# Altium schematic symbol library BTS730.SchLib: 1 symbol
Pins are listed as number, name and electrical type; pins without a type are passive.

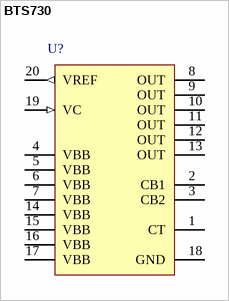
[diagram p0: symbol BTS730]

## BTS730
designator U?
Smart High-Side Power Switch, 1 Channel, 3 A Load Current, -40 to 150 degC, PG-DSO-20-31, Reel, Green; Manufacturer: Infineon; PartNumber: BTS730; Channels: 1; Green: TRUE; Group: Automotive Qualified; Load Current (typ): 3 A; Ptot (max): 3 W; Recommended Operating Voltage Max.: 16.9 V; Recommended Operating Voltage Min.: 5.9 V; RON @ 25degreesC: 70 mOhm; RON(max) @ 150degreesC: 140 mOhm
footprint INF-PG-DSO-20-31_N (SOP, 20-Leads, Body 12.7x7.5mm, Pitch 1.27mm, IPC High Density)
footprint INF-PG-DSO-20-31_L (SOP, 20-Leads, Body 12.7x7.5mm, Pitch 1.27mm, IPC High Density)
footprint INF-PG-DSO-20-31_M (SOP, 20-Leads, Body 12.7x7.5mm, Pitch 1.27mm, IPC Low Density)
pins: 1 CT "Timing capacitor for frequency.", 2 CB1 "Bootstrap capacitor", 3 CB2 "Bootstrap capacitor", 4 VBB (power) "Supply voltage (Leadframe connected)", 5 VBB (power) "Supply voltage (Leadframe connected)", 6 VBB (power) "Supply voltage (Leadframe connected)", 7 VBB (power) "Supply voltage (Leadframe connected)", 8 OUT (power) "Output", 9 OUT (power) "Output", 10 OUT (power) "Output", 11 OUT (power) "Output", 12 OUT (power) "Output", 13 OUT (power) "Output", 14 VBB (power) "Supply voltage (Leadframe connected)", 15 VBB (power) "Supply voltage (Leadframe connected)", 16 VBB (power) "Supply voltage (Leadframe connected)", 17 VBB (power) "Supply voltage (Leadframe connected)", 18 GND (power) "Ground", 19 VC (in) "Voltage for PWM-Control", 20 VREF (out) "Reference Voltage."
